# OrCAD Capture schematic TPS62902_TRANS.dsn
size E; title: TPS62902, 3-V to 17-V, High Efficiency and Low IQ; rev: 1.0; note: Datasheet: SLVSFM1                    EVM: SNVU745A; note: Synchronous Step Down Converter
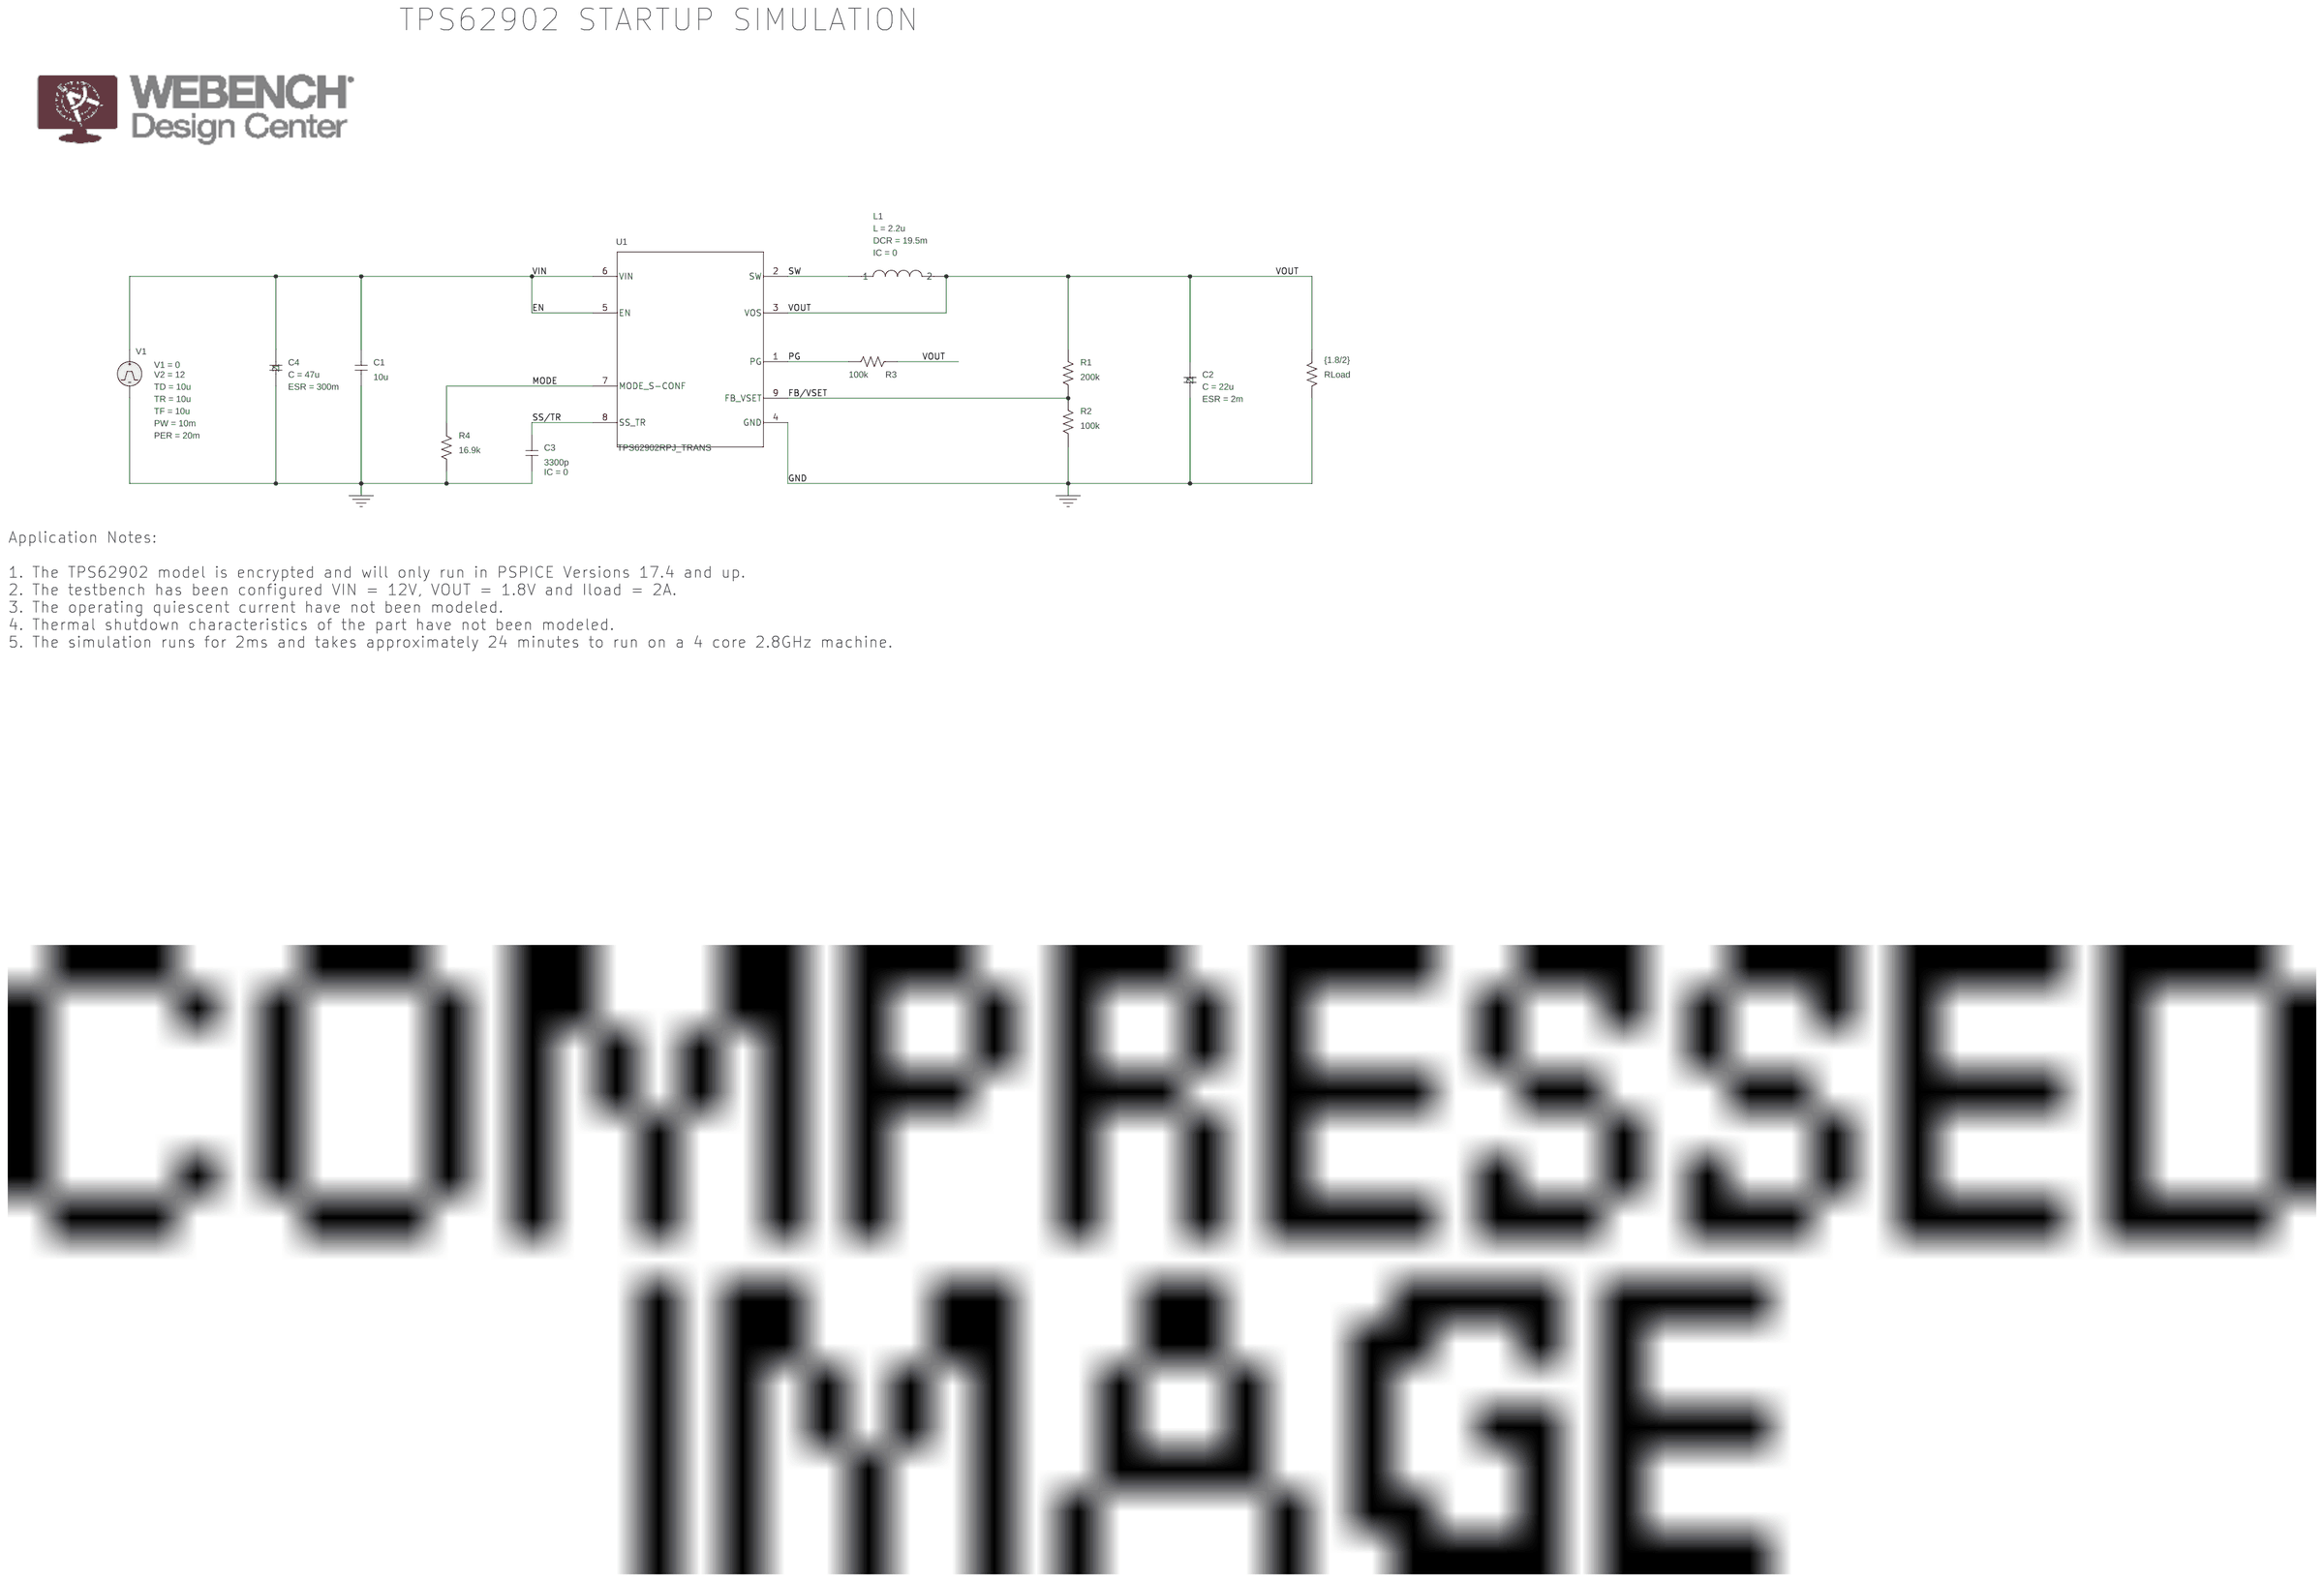
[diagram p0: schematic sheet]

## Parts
C1  10u  [RAD/CK05]
C2  CESR
C3  3300p  [RAD/CK05]
C4  CESR
L1  LDCR
R1  200k  [AX/RC05]
R2  100k  [AX/RC05]
R3  100k  [AX/RC05]
R4  16.9k  [AX/RC05]
RLoad  {1.8/2}  [AX/RC05]
U1  TPS62902RPJ_TRANS  [RPJ0009A]
V1  VPULSE

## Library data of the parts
C1 = C
C2 = CESR: C: 22u; ESR: 2m; IC: 0; PSpiceTemplate: X^@REFDES %1 %2 @MODEL PARAMS: ?C|C=@C||C=10U| ?ESR|ESR=@ESR||ESR=2M| ?IC|IC=@IC||IC=1N| ?X|X=@X||X=1|; X: 1
C3 = C: IC: 0
C4 = CESR_1: C: 47u; ESR: 300m; IC: 0; PSpiceTemplate: X^@REFDES %1 %2 @MODEL PARAMS: ?C|C=@C||C=10U| ?ESR|ESR=@ESR||ESR=2M| ?IC|IC=@IC||IC=1N| ?X|X=@X||X=1|; X: 1
L1 = LDCR: DCR: 19.5m; IC: 0; L: 2.2u
R1-R4 RLoad = R
U1 = TPS62902RPJ_TRANS
V1 = VPULSE: PER: 20m; PW: 10m; TD: 10u; TF: 10u; TR: 10u; V1: 0; V2: 12

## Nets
0: C1.2 C2.2 C3.2 C4.2 R2.1 R4.2 RLoad.2 U1.4(GND) V1.2(-)
EN: C1.1 C4.1 U1.5(EN) U1.6(VIN) V1.1(+)
FB/VSET: R1.1 R2.2 U1.9(FB_VSET)
MODE: R4.1 U1.7(MODE_S-CONF)
PG: R3.2 U1.1(PG)
SS/TR: C3.1 U1.8(SS_TR)
SW: L1.1 U1.2(SW)
VOUT: C2.1 L1.2 R1.2 R3.1 RLoad.1 U1.3(VOS)

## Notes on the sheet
- TPS62902 STARTUP SIMULATION
- Application Notes:
  1. The TPS62902 model is encrypted and will only run in PSPICE Versions 17.4 and up.
  2. The testbench has been configured VIN = 12V, VOUT = 1.8V and Iload = 2A.
  3. The operating quiescent current have not been modeled.
  4. Thermal shutdown characteristics of the part have not been modeled.
  5. The simulation runs for 2ms and takes approximately 24 minutes to run on a 4 core 2.8GHz machine.
